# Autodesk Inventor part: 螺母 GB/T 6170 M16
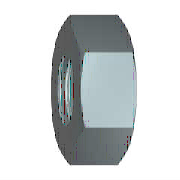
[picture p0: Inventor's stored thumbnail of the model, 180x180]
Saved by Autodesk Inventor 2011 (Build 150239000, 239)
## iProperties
Created: 2010-02
Part Number: 螺母 GB/T 6170 M16
Material: 低炭钢
Description: 1 型六角螺母
Document SubType Name: Modeling
Standard: GB/T 6170-2000
Designer: Administrator
Standard Revision: 2000
Standards Organization: GB
Language: zh-CN
Size Designation: M16
Categories: <MemberInstance><Categories><Category DisplayName="紧固件" InternalName="e4da775c-781d-43d5-af7c-5136215cf5a6" Mnemonic="FSTN"><Category DisplayName="螺母" InternalN
Density: 1 g/cm^3
IsCustomPart: 1
Author: Administrator
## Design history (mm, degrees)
body "Solid1"
sketch "Sketch1"
  geometry: L1 (-13.856, 0)-(-6.928, 12); L2 (-6.928, 12)-(6.928, 12); L3 (6.928, 12)-(13.856, 0); L4 (13.856, 0)-(6.928, -12); L5 (6.928, -12)-(-6.928, -12); L6 (-6.928, -12)-(-13.856, 0); 2 further points
  constraints: 12 end point, 1 coincident, 1 horizontal, 11 other
  dimensions: "d0" = 27.71281 distance of L3.end L1.start (= 1.1547 x SW)
workaxis "Work Axis1"
workplane "Work Plane1"
extrude "Body" new body sketch "Sketch1" distance "d1" = 14.8 (= KOH); taper "d2" = 0 deg
sketch "Sketch2"
  geometry: L1 (0, 6.928)-(0, 13.856) reference; L2 (0, 13.856)-(14.8, 13.856) reference; L3 (14.8, 6.928)-(14.8, 13.856) reference; L4 (-2.96, 0)-(17.76, 0) reference; L5 (1.072, 13.856)-(0, 12); L6 (13.728, 13.856)-(14.8, 12)
  constraints: 4 end point, 4 point on line
  dimensions: "d3" = 30 deg angle of L1 L5 (= ANG1); "d4" = 30 deg angle of L3 L6 (= ANG2); "d5" = 24 diameter of L5.end L4 (= SW0); "d6" = 24 diameter of L6.end L4 (= SW01)
revolve "Chamfer1" stored, may be unused: angle "d7" = 90 deg
sketch "Sketch3"
  geometry: A1 r 12 centre (0, 0) between (-6, -10.392) and (6, -10.392) reference; 1 further point
  constraints: 1 coincident
hole "Thread" sketch "Sketch3" diameter "d25" = 13.835; stored, may be unused: countersink angle "d29" = 82 deg, drill point angle "d31" = 118 deg; dims "d26" = 6, "d27" = 4, "d28" = 2, "d30" = 8
chamfer "Chamfer2" distance "d8" = 1.08253 (= -0.5 x GD1 + 0.5 x NND); stored, may be unused: angle "d9" = 30 deg, second distance "d40" = 1.08253 (= -0.5 x GD1 + 0.5 x NND)
chamfer "Chamfer3" distance "d10" = 1.08253 (= -0.5 x GD1 + 0.5 x NND); stored, may be unused: angle "d11" = 30 deg, second distance "d41" = 1.08253 (= -0.5 x GD1 + 0.5 x NND)
other parameters: "ANG1" = 30 deg [user parameter; used in 1 equation term], "ANG2" = 30 deg [user parameter; used in 1 equation term], "NND" = 16 [user parameter; used in 4 equation terms], "KOH" = 14.8 [user parameter; used in 1 equation term], "SW" = 24 [user parameter; used in 4 equation terms], "SW0" = 24 (= SW) [user parameter; used in 1 equation term], "SW01" = 24 (= SW) [user parameter; used in 1 equation term], "GD1" = 13.83494 (computed from THREADDIA, PTC, TOA) [user parameter; used in 4 equation terms], "d13" = 0, "d14" = 0, "d39" = 0, "d42" = 0, "GUL" = 1.08253 (= 0.541266 x PTC) [user parameter], "TPU" = 5 (computed from PTC) [user parameter], "THREADDIA" = 16 [user parameter; used in 1 equation term], "TOA" = 30 deg [user parameter; used in 1 equation term], "PTC" = 2 [user parameter; used in 4 equation terms], "E0" = 27.72 (= 1.155 x SW) [user parameter], "GAL" = 1.08253 (= 0.541266 x PTC) [user parameter]
